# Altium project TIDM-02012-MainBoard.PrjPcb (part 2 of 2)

## Sheet TIDM-02012_Communication.SchDoc
size 431 x 279 mm; Date: Not shown in title block; ApprovedBy: Not shown in title block; CheckedBy: Not shown in title block; Author: Not shown in title block; CompanyName: Not shown in title block; Engineer: Not shown in title block; Organization: Not shown in title block; Address1: Not shown in title block; Address2: Not shown in title block; Address3: Not shown in title block; Address4: Not shown in title block; DocumentNumber: 2; Revision: Use project parameter SCH_Rev; SheetNumber: 5; SheetTotal: 6; PageSetup: Record=PageOptions¦CenterHorizontal=True¦CenterVertical=True¦PrintScale=1.00¦XCorrection=1.00¦YCorrection=1.00¦PrintKind=0¦BorderSize=5000000¦LeftOffset=0¦BottomOffset=0¦Orientation=2¦PaperLength=1000¦PaperWidth=1000¦Scale=100¦PaperSource=15¦PrintQuality=600¦MediaType=1¦DitherType=10¦PaperKind=Letter¦PrintScaleMode=1
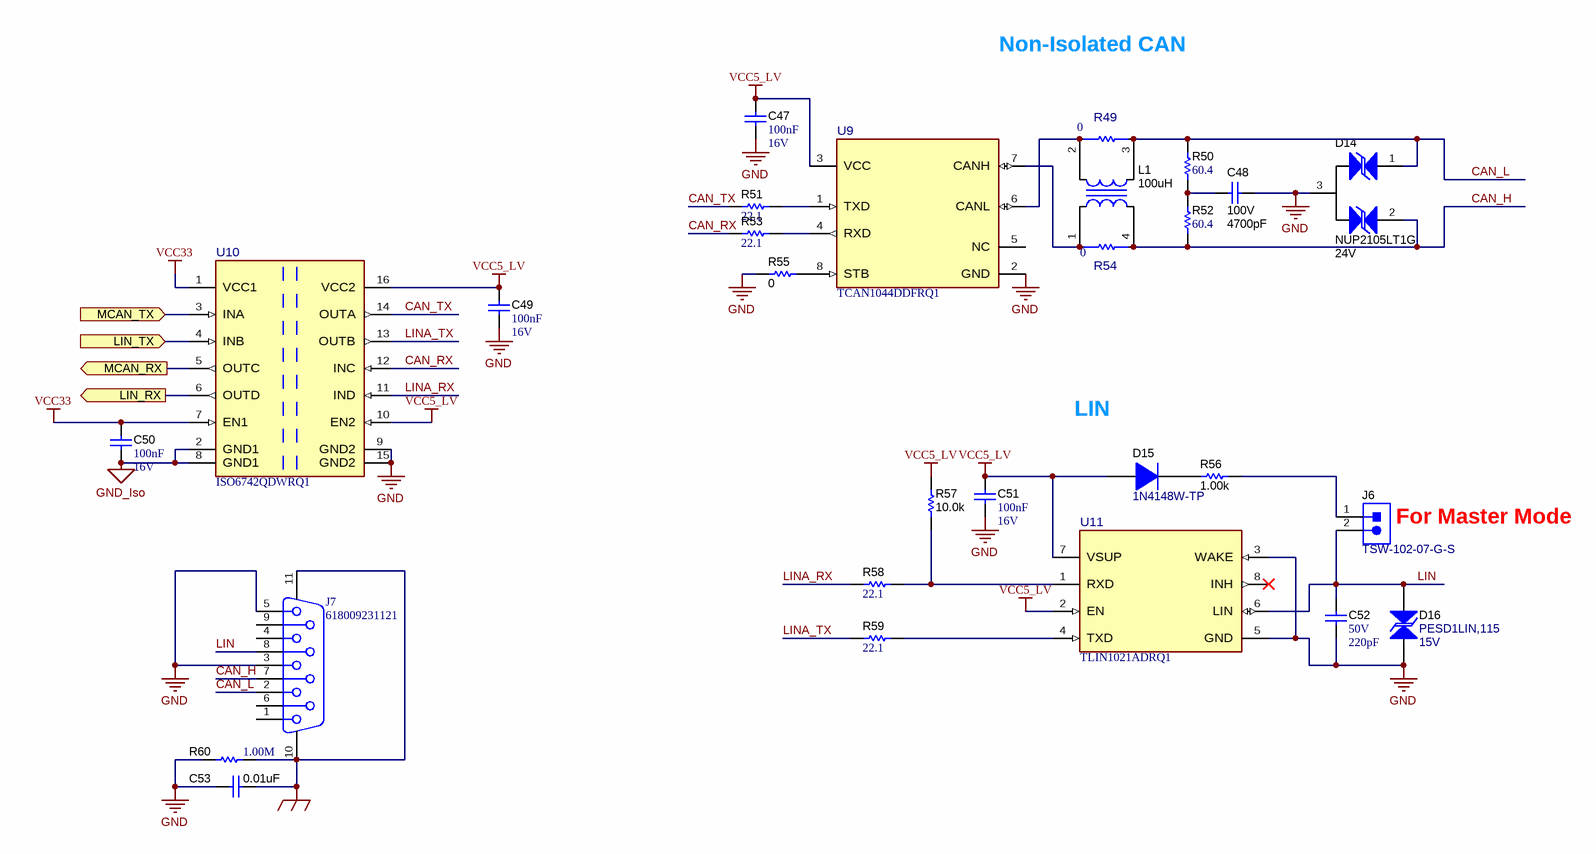
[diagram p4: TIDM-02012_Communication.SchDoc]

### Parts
C47  Cap_F: 100nF  VDC_V: 16V  [0603]  (hidden comment: C0603C104J4RACTU)
C48  VDC_V: 100V  ValueDisplayed: 4700pF  [0603]  (hidden comment: CGA3E2X7R2A472K080AA)
C49  Cap_F: 100nF  VDC_V: 16V  [0603]  (hidden comment: C0603C104J4RACTU)
C50  Cap_F: 100nF  VDC_V: 16V  [0603]  (hidden comment: C0603C104J4RACTU)
C51  Cap_F: 100nF  VDC_V: 16V  [0603]  (hidden comment: C0603C104J4RACTU)
C52  VDC_V: 50V  ValueDisplayed: 220pF  [0603]  (hidden comment: 06035A221JAT2A)
C53  ValueDisplayed: 0.01uF  [1206]  (hidden comment: 12061C103JAT2A)
D14  NUP2105LT1G  value 24V  [SOT-23]
D15  1N4148W-TP  [SOD-123]
D16  PESD1LIN,115  value 15V  [SOD-323-Bi]
J6  TSW-102-07-G-S  [TSW-102-07-G-S]
J7  618009231121  [Wurth_618009231121]
L1  ValueDisplayed: 100uH  [ACT45B]  (hidden comment: ACT45B-101-2P-TL003)
R49  value 0  [FP-CRCW06030000Z0EBC_0603-MFG]  (hidden comment: CRCW06030000Z0EBC)
R50  ValueDisplayed: 60.4  [0603]  (hidden comment: RC0603FR-0760R4L)
R51  ValueDisplayed: 22.1  [0603]  (hidden comment: RC0603FR-0722R1L)
R52  ValueDisplayed: 60.4  [0603]  (hidden comment: RC0603FR-0760R4L)
R53  ValueDisplayed: 22.1  [0603]  (hidden comment: RC0603FR-0722R1L)
R54  value 0  [FP-CRCW06030000Z0EBC_0603-MFG]  (hidden comment: CRCW06030000Z0EBC)
R55  ValueDisplayed: 0  [0603]  (hidden comment: RMCF0603ZT0R00)
R56  ValueDisplayed: 1.00k  [0805_HV]  (hidden comment: ERJ-6ENF1001V)
R57  ValueDisplayed: 10.0k  [0603_HV]  (hidden comment: RC0603FR-0710KL)
R58  ValueDisplayed: 22.1  [0603]  (hidden comment: RC0603FR-0722R1L)
R59  ValueDisplayed: 22.1  [0603]  (hidden comment: RC0603FR-0722R1L)
R60  ValueDisplayed: 1.00M  [0805_HV]  (hidden comment: ERJ-6ENF1004V)
U9  TCAN1044DDFRQ1  [DDF0008A-MFG]
U10  ISO6742QDWRQ1  [DW0016A-MFG]
U11  TLIN1021ADRQ1  [D0008A-MFG]

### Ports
LIN_RX (out), LIN_TX (in), MCAN_RX (out), MCAN_TX (in)

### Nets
GND: C47.2 C48.1 C49.2 C51.2 C52.2 C53.2 D14.3 D16.1 J7.3 J7.5 R55.1 R60.1 U9.2(GND) U10.9(GND2) U10.15(GND2) U11.3(WAKE) U11.5(GND)
GND_Iso: C50.2 U10.2(GND1) U10.8(GND1)  [project net GND_MCU]
SHIELD_GND: C53.1 J7.10 J7.11 R60.2
VCC5_LV: C47.1 C49.1 C51.1 D15.2(A) R57.2 U9.3(VCC) U10.10(EN2) U10.16(VCC2) U11.2(EN) U11.7(VSUP)
VCC33: C50.1 U10.1(VCC1) U10.7(EN1)
CAN_H: D14.2 J7.7 L1.4 R52.1 R54.2
CAN_L: D14.1 J7.2 L1.3 R49.2 R50.2
CAN_RX: R53.1 U10.12(INC)
CAN_TX: R51.1 U10.14(OUTA)
LIN: C52.1 D16.2 J6.2 J7.8 U11.6(LIN)
LIN_RX: U10.6(OUTD) ; port LIN_RX
LIN_TX: U10.4(INB) ; port LIN_TX
LINA_RX: R58.1 U10.11(IND)
LINA_TX: R59.1 U10.13(OUTB)
MCAN_RX: U10.5(OUTC) ; port MCAN_RX
MCAN_TX: U10.3(INA) ; port MCAN_TX
NetC48_2: C48.2 R50.1 R52.2
NetD15_1: D15.1(K) R56.2
NetJ6_1: J6.1 R56.1
NetL1_1: L1.1 R54.1 U9.7(CANH)
NetL1_2: L1.2 R49.1 U9.6(CANL)
NetR51_2: R51.2 U9.1(TXD)
NetR53_2: R53.2 U9.4(RXD)
NetR55_2: R55.2 U9.8(STB)
NetR57_1: R57.1 R58.2 U11.1(RXD)
NetR59_2: R59.2 U11.4(TXD)

Not connected (* = marked no-connect by the designer): J7 1 4 6 9; U9 5(NC); U11 8(INH)*

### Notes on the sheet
- Non-Isolated CAN
- LIN
- (near J6) For Master Mode

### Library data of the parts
C47 C49-C51 = CMP-0006857-4: CAP, CERM, 0.1 uF, 16 V, +/- 5%, X7R, 0603; Manufacturer: Kemet; TaMin_C: -55°C; Polarized: N; SizeAreaWB_mm2: 4.68; Value1: Unknown; U/M: EA; Value: 0.1uF; TaMax_C: 125°C; SizeZ_mm: 1; SizeX_mm: 1.6; SizeY_mm: 0.8; SizeArea_mm2: 1.28; AEC Category: Q200
C48 = CMP-0007088-4: CAP, CERM, 4700 pF, 100 V, +/- 10%, X7R, AEC-Q200 Grade 1, 0603; Manufacturer: TDK; TaMin_C: -55°C; ESR_ohm: 4.69862d; Polarized: N; SizeAreaWB_mm2: 4.68; Value1: 0.469862 ohm; U/M: EA; Value: 4700pF; TaMax_C: 125°C; SizeZ_mm: 1; SizeX_mm: 1.6; SizeY_mm: 0.8; SizeArea_mm2: 1.28; AEC Qualified: Y; Cap_F: 4.7nF; IRMS_A: 3.2335dA; AEC Category: Q200
C52 = CMP-0006777-4: CAP, CERM, 220 pF, 50 V, +/- 5%, C0G/NP0, 0603; Manufacturer: AVX; TaMin_C: -55°C; ESR_ohm: 0.083; Polarized: N; SizeAreaWB_mm2: 4.68; Value1: 0.083 ohm; U/M: EA; Value: 220pF; TaMax_C: 125°C; SizeZ_mm: 1; SizeX_mm: 1.6; SizeY_mm: 0.8; SizeArea_mm2: 1.28; AEC Category: Q200
C53 = CMP-0008484-2: CAP, CERM, 0.01 uF, 100 V, +/- 5%, X7R, 1206; Manufacturer: AVX; TaMin_C: -55°C; ESR_ohm: 1.19d; Polarized: N; SizeAreaWB_mm2: 10.92; Value1: 0.119 ohm; U/M: EA; Value: 0.01uF; TaMax_C: 125°C; SizeZ_mm: 1.35; SizeX_mm: 3.2; SizeY_mm: 1.6; Value2: 100V; SizeArea_mm2: 5.12; Cap_F: 10nF; AEC Category: Q200
D14 = CMP-0005919-3: Diode, TVS, Bi, 24 V, SOT-23; Manufacturer: ON Semiconductor; SizeAreaWB_mm2: 14; Value1: 350W; SizeZ_mm: 1.1; SizeX_mm: 2.5; SizeY_mm: 3; SizeArea_mm2: 7.5; AEC Category: Q101
D15 = CMP-0076974-2: Diode, Switching, 100 V, 0.15 A, SOD-123; Manufacturer: Micro Commercial Components; Io_A: 150mA; SizeX_mm: 3.85; SizeY_mm: 1.7; Green_REACh: Incomplete; AEC Category: Q101; TJmax_C: 150°C; Value1: 0.15A; Vf_V: 1.25V; Value: 100V; SizeZ_mm: 1.35; SizeArea_mm2: 6.545; SizeAreaWB_mm2: 13.095; Green_Lifecycle: Not Set
D16 = CMP-0005821-3: Diode, TVS, Bi, 15 V, SOD-323; Manufacturer: NXP Semiconductor; SizeAreaWB_mm2: 8.695; Ppk: 160W; SizeZ_mm: 1; SizeY_mm: 1.35; SizeArea_mm2: 3.645; SizeX_mm: 2.7; AEC Category: Q101
J6 = CMP-0075405-3: Header, 100mil, 2x1, Gold, TH; Manufacturer: Samtec; Current_A: 6.3A; Green_Lifecycle: Active; Pitch_mm: 2.54; Cert_CSA: Y; Cert_VDE: N; Green_REACh: Passed; Row_Count: 1; Gender: Male; Voltage_V: 550V
J7 = CMP-0054820-2: Receptacle, D-Sub, 9 Position, R/A, TH; Manufacturer: Wurth Elektronik; CNHeader: FALSE; Current_A: 3A; Gender: Female; Voltage_V: 125V; Row_Count: 2; Pitch_mm: 2.77; ContactFinish: Gold; CT: TRUE; Cert_UL: Y
L1 = CMP-0062430-2: Inductor, Ferrite, 100 uH, 0.15 A, 2 ohm, SMD; Manufacturer: TDK; Isat: 0.15A @ % inductance drop; Green_Lifecycle: Active; SizeAreaWB_mm2: 23.1; DCR_ohm: 2; Green_REACh: Passed; Value1: 2 ohm; Value: 100uH; Imax_A: 1.5dA; SizeZ_mm: 3; SizeX_mm: 4.5; SizeY_mm: 3.2; Value2: 0.15A; SizeArea_mm2: 14.4; Ind_H: 100µH; AEC Category: Q200
R49 R54 = CMP-0093667-1: CRCW Thick Film Commodity Chip Resistor Jumper 0603 Size 0 Ohm 0.1 W 2-Pin SMD Paper T/R; Manufacturer: Vishay; SizeZ_mm: 0.55mm; VDC_V: 75V; Power_W: 100mW; AEC Qualified: No
R50 R52 = CMP-0023213-5: RES, 60.4, 1%, 0.1 W, 0603; Manufacturer: Yageo; Power_W: 100mW; TempCo: 100 ppm/C; Value_Code: 60R4; Value: 60.4; EIA_Code: E96; SizeX_mm: 1.6; SizeY_mm: 0.8; SizeZ_mm: 1; Value2: 0.1W; SizeArea_mm2: 1.28; AEC Qualified: N; VDC_V: 75V; AEC Category: Q200; SizeAreaWB_mm2: 4.68
R51 R53 R58 R59 = CMP-0022926-4: RES, 22.1, 1%, 0.1 W, 0603; Manufacturer: Yageo; Power_W: 100mW; TempCo: 100 ppm/C; Value_Code: 22R1; Value: 22.1; EIA_Code: E96; SizeX_mm: 1.6; SizeY_mm: 0.8; SizeZ_mm: 1; Value2: 0.1W; SizeArea_mm2: 1.28; AEC Qualified: N; VDC_V: 75V; AEC Category: Q200; SizeAreaWB_mm2: 4.68
R55 = CMP-0023343-3: RES, 0, 1%, 0.1 W, AEC-Q200 Grade 0, 0603; Manufacturer: Stackpole Electronics Inc; Power_W: 100mW; TempCo: ppm/C; U/M: EA; Value: 0; SizeX_mm: 1.6; SizeY_mm: 0.8; SizeZ_mm: 1; Value2: 0.1W; SizeArea_mm2: 1.28; AEC Qualified: Y; AEC Category: Q200
R56 = CMP-0021519-3: RES, 1.00 k, 1%, 0.125 W, AEC-Q200 Grade 0, 0805; Manufacturer: Panasonic; Power_W: 125mW; TempCo: 100 ppm/C; Value_Code: 1k00; Value: 1.00k; EIA_Code: E96; Res_ohm: 1k; SizeX_mm: 2; SizeY_mm: 1.25; SizeZ_mm: 1.45; Value2: 0.125W; SizeArea_mm2: 2.5; AEC Qualified: Y; AEC Category: Q200; AEC Grade: 0; SizeAreaWB_mm2: 6.75
R57 = CMP-0022746-5: RES, 10.0 k, 1%, 0.1 W, 0603; Manufacturer: Yageo; Value: 10.0k; Res_ohm: 10k; Value_Code: 10k0; Power_W: 100mW; Value2: 0.1W; VDC_V: 75V; TempCo: 100 ppm/C; EIA_Code: E96; AEC Category: Q200; AEC Qualified: N; SizeArea_mm2: 1.28; SizeX_mm: 1.6; SizeY_mm: 0.8; SizeZ_mm: 1; SizeAreaWB_mm2: 4.68
R60 = CMP-0021522-3: RES, 1.00 M, 1%, 0.125 W, AEC-Q200 Grade 0, 0805; Manufacturer: Panasonic; Power_W: 125mW; TempCo: 100 ppm/C; Value_Code: 1M00; Value: 1.00Meg; EIA_Code: E96; Res_ohm: 1M; SizeX_mm: 2; SizeY_mm: 1.25; SizeZ_mm: 1.45; Value2: 0.125W; SizeArea_mm2: 2.5; AEC Qualified: Y; AEC Category: Q200; AEC Grade: 0; SizeAreaWB_mm2: 6.75
U9 = CMP-0089901-1: Automotive High Speed CAN Transceiver; Manufacturer: Texas Instruments; Min Supply Voltage: 4.5V; TaMin_C: -40°C; AEC Grade: Grade 1; Standoff Height: 0mm; SizeZ_mm: 1.1mm; TaMax_C: +125°C; Max Supply Voltage: 5.5V; Nominal Supply Current: 5-180mA; TJmax_C: +150°C; AEC Qualified: Yes
U10 = CMP-0093723-1: General-Purpose Reinforced Quad-Channel Automotive Digital Isolators with Robust EMC; Manufacturer: Texas Instruments; TaMin_C: -40°C; SizeZ_mm: 2.65mm; Standoff Height: 0.1mm; Min Supply Voltage: 1.71V; AEC Grade: Grade 1; TJmax_C: +150°C; AEC Qualified: Yes; Max Supply Voltage: 5.5V; TaMax_C: +125°C
U11 = CMP-0091357-1: Fault-Protected LIN Transceiver with Inhibit and Wake; Manufacturer: Texas Instruments; TJmax_C: +150°C; SizeZ_mm: 1.75mm; Max Supply Voltage: 36V; AEC Grade: Grade 1; AEC Qualified: Yes; Standoff Height: 0.11mm; Nominal Supply Current: 300-1200uA; Min Supply Voltage: 4.5V

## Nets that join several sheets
GND: TIDM-02012_Power_Supply (20 pins), TIDM-02012_Communication (17 pins)
GND_MCU: TIDM-02012_CoverSheet (49 pins), TIDM-02012_Power_Supply (21 pins), U (5 pins), W (5 pins), V (5 pins), TIDM-02012_Communication (C50.2 U10.2 U10.8)
P5V_MCU: TIDM-02012_CoverSheet (8 pins), TIDM-02012_Power_Supply (C41.1 R46.2 R47.2 U7.4)
PGND: TIDM-02012_CoverSheet (10 pins), TIDM-02012_Power_Supply (6 pins), U (C19U.2 R30U.1), W (C19W.2 R30W.1), V (C19V.2 R30V.1)
VBUS: TIDM-02012_CoverSheet (5 pins), U (C8U.1 Q1U.2), W (C8W.1 Q1W.2), V (C8V.1 Q1V.2)
VCC5_LV: TIDM-02012_Power_Supply (C45.1 R48.2 R74.2 U8.4), TIDM-02012_Communication (10 pins)
VCC33: TIDM-02012_CoverSheet (21 pins), TIDM-02012_Power_Supply (C26.1 R41.2 R42.2 U6.4), U (C20U.2 D7U.1 J12U.4 U4U.5), W (C20W.2 D7W.1 J12W.4 U4W.5), V (C20V.2 D7V.1 J12V.4 U4V.5), TIDM-02012_Communication (C50.1 U10.1 U10.7)
VDD_Driver: TIDM-02012_Power_Supply (8 pins), U (J12U.2), W (J12W.2), V (J12V.2)
DC-: TIDM-02012_CoverSheet (NT1.1 R1.2 R2.2), U (C8U.2 NT4U.1 R24U.1 R25U.1), W (C8W.2 NT4W.1 R24W.1 R25W.1), V (C8V.2 NT4V.1 R24V.1 R25V.1)
EN_DRV: TIDM-02012_CoverSheet (U12.6), U (J12U.6), W (J12W.6), V (J12V.6)
Ifb_U: TIDM-02012_CoverSheet (J1.15), U (C38U.1 R43U.2)
Ifb_V: TIDM-02012_CoverSheet (J1.18), V (C38V.1 R43V.2)
Ifb_W: TIDM-02012_CoverSheet (J1.21), W (C38W.1 R43W.2)
LIN_RX: TIDM-02012_CoverSheet (J1.74), TIDM-02012_Communication (U10.6)
LIN_TX: TIDM-02012_CoverSheet (J1.72), TIDM-02012_Communication (U10.4)
MCAN_RX: TIDM-02012_CoverSheet (J1.80), TIDM-02012_Communication (U10.5)
MCAN_TX: TIDM-02012_CoverSheet (J1.82), TIDM-02012_Communication (U10.3)
PWM1A: TIDM-02012_CoverSheet (J1.49), U (J12U.5)
PWM1B: TIDM-02012_CoverSheet (J1.51), U (J12U.3)
PWM2A: TIDM-02012_CoverSheet (J1.53), V (J12V.5)
PWM2B: TIDM-02012_CoverSheet (J1.55), V (J12V.3)
PWM3A: TIDM-02012_CoverSheet (J1.50), W (J12W.5)
PWM3B: TIDM-02012_CoverSheet (J1.52), W (J12W.3)
V_bias_1v65: TIDM-02012_CoverSheet (5 pins), U (C21U.2 R33U.1), W (C21W.2 R33W.1), V (C21V.2 R33V.1)
Vfb_U: TIDM-02012_CoverSheet (J1.17), U (C39U.1 R45U.2)
Vfb_V: TIDM-02012_CoverSheet (J1.20), V (C39V.1 R45V.2)
Vfb_W: TIDM-02012_CoverSheet (J1.23), W (C39W.1 R45W.2)

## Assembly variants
001: not fitted C1 C4 C18U C18V C18W C21U C21V C21W C32 R19 R49 R54 R69 R71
